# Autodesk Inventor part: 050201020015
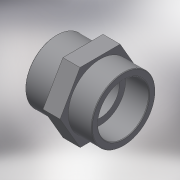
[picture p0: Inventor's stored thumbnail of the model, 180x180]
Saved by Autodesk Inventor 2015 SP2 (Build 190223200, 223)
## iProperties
Created: 2017-10
Part Number: 050201020015
Material: Generic
Description: PLASSON THREADED REDUCER PVC 2"-1.1/2"F
Document SubType Name: Modeling
Designer: KIM
Density: 1 g/cm^3
Appearance: Default
Author: KIM
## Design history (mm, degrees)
derived "050201.ipt"
feature "Solid1::050201.ipt"
tag "TaggingFeature1"
body "Solid1"
other parameters: "d0" = 63, "d1" = 44.845, "d2" = 65, "d4" = 35.876, "d5" = 26, "d6" = 22, "d8" = 59.614, "d10" = 22, "d13" = 0, "d14" = 0.59614, "d15" = 16, "d16" = 47.6912, "d17" = 58.2985, "R_" = 59.614, "C_" = 65, "B_" = 16, "lt_" = 22, "H_" = 63, "G_" = 44.845, "lt_1" = 26
